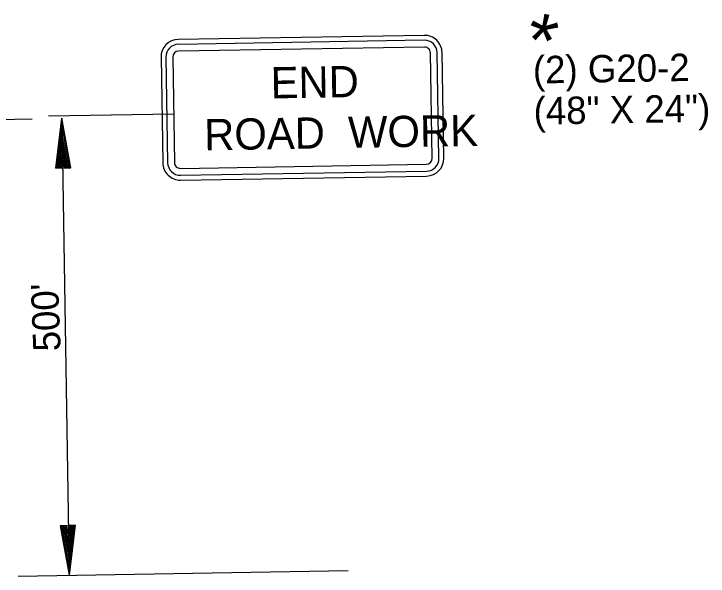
# Model space of a CAD drawing. Extents: x 1676063 to 1678026, y 228339 to 229904.
# Drawn here: x 1677171.5 to 1677323.5, y 229285.7 to 229408.7 of the extents above; entities that cross this region are included whole.
import ezdxf

# ---------------------------------------------------------------- set-up
doc = ezdxf.new("R2010")
doc.units = 0
for name, color, linetype in [('P_TC_Signs_Temporary', 7, 'Continuous'), ('R_Annotation', 7, 'Continuous'), ('R_Draft', 7, 'Continuous')]:
    doc.layers.add(name, color=color, linetype=linetype)

msp = doc.modelspace()

# ---------------------------------------------------------------- linework, layer by layer
at = {"layer": 'P_TC_Signs_Temporary'}
for p, q in [((1677261.37, 229404), (1677207.52, 229403.1)), ((1677261.39, 229402.93), (1677207.53, 229402.03)), ((1677261.42, 229401.43), (1677207.56, 229400.54)), ((1677264.6, 229377.11), (1677264.22, 229400.2)), ((1677265.67, 229377.13), (1677265.28, 229400.21)), ((1677203.73, 229399.19), (1677204.12, 229376.11)), ((1677204.8, 229399.21), (1677205.18, 229376.13)), ((1677206.3, 229399.24), (1677206.68, 229376.15)), ((1677263.1, 229377.09), (1677262.72, 229400.17)), ((1677207.98, 229374.89), (1677261.84, 229375.79)), ((1677208.01, 229373.4), (1677261.87, 229374.29)), ((1677208.03, 229372.33), (1677261.88, 229373.22))]:
    msp.add_line(p, q, dxfattribs=at)
for centre, radius, start, end in [((1677261.44, 229400.15), 3.85, 0.9497, 90.9497), ((1677207.58, 229399.26), 3.85, 90.9497, 180.9497), ((1677207.58, 229399.26), 2.78, 90.9497, 180.9497), ((1677261.44, 229400.15), 2.78, 0.9497, 90.9497), ((1677207.58, 229399.26), 1.28, 90.9497, 180.9497), ((1677261.44, 229400.15), 1.28, 0.9497, 90.9497), ((1677207.96, 229376.17), 3.85, 180.9497, 270.9497), ((1677207.96, 229376.17), 2.78, 180.9497, 270.9497), ((1677207.96, 229376.17), 1.28, 180.9497, 270.9497), ((1677261.82, 229377.07), 1.28, 270.9497, 0.9497), ((1677261.82, 229377.07), 2.78, 270.9497, 0.9497), ((1677261.82, 229377.07), 3.85, 270.9497, 0.9497)]:
    msp.add_arc(centre, radius, start, end, dxfattribs=at)
at = {"layer": 'R_Draft'}
for p, q in [((1677179.07, 229386.38), (1677206.55, 229386.83)), ((1677165.65, 229385.57), (1677175.55, 229385.74)), ((1677180.71, 229374.92), (1677181.99, 229385.85)), ((1677181.99, 229385.85), (1677183.64, 229285.86)), ((1677183.97, 229375.02), (1677181.99, 229385.85)), ((1677180.98, 229374.93), (1677182.05, 229384.03)), ((1677183.7, 229375.01), (1677182.05, 229384.03)), ((1677181.26, 229374.94), (1677182.11, 229382.16)), ((1677183.42, 229375.01), (1677182.11, 229382.16)), ((1677181.53, 229374.95), (1677182.17, 229380.35)), ((1677183.15, 229375), (1677182.17, 229380.35)), ((1677181.81, 229374.96), (1677182.23, 229378.5)), ((1677182.87, 229374.99), (1677182.23, 229378.5)), ((1677182.08, 229374.96), (1677182.29, 229376.69)), ((1677182.6, 229374.98), (1677182.29, 229376.69)), ((1677180.71, 229374.92), (1677183.97, 229375.02)), ((1677184.92, 229296.79), (1677181.65, 229296.68)), ((1677181.65, 229296.68), (1677183.64, 229285.86)), ((1677181.93, 229296.69), (1677183.58, 229287.68)), ((1677182.21, 229296.7), (1677183.52, 229289.54)), ((1677182.48, 229296.71), (1677183.46, 229291.36)), ((1677182.76, 229296.72), (1677183.4, 229293.2)), ((1677183.03, 229296.73), (1677183.34, 229295.02)), ((1677183.54, 229296.75), (1677183.34, 229295.02)), ((1677183.82, 229296.75), (1677183.4, 229293.2)), ((1677184.1, 229296.76), (1677183.46, 229291.36)), ((1677184.37, 229296.77), (1677183.52, 229289.54)), ((1677184.65, 229296.78), (1677183.58, 229287.68)), ((1677184.92, 229296.79), (1677183.64, 229285.86)), ((1677172.45, 229285.67), (1677244.75, 229286.87))]:
    msp.add_line(p, q, dxfattribs=at)

# ---------------------------------------------------------------- texts
at = {"layer": 'P_TC_Signs_Temporary'}
for s, p in [('END', (1677227.79, 229390.19)), ('ROAD  WORK', (1677213.24, 229378.83))]:
    msp.add_text(s, height=6.84, rotation=0.9497, dxfattribs=at).set_placement(p)
at = {"layer": 'R_Annotation'}
for s, height, rotation, p in [('*', 12, 135.9497, (1677295.96, 229409.72)), ('(2) G20-2', 6, 0.9497, (1677285.22, 229393.45)), ('(48" X 24")', 6, 0.9497, (1677285.37, 229384.45)), ("500'", 6, 92.1801, (1677181.77, 229334.95))]:
    msp.add_text(s, height=height, rotation=rotation, dxfattribs=at).set_placement(p)

doc.saveas('drawing.dxf')
